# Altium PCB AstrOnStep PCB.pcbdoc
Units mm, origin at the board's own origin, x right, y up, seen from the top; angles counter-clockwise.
Board outline 107.04 x 79.7 mm, 4 copper layers (Top Layer, Inner1, Inner2, Bottom Layer); 79 components, 101 nets, 389 pads, 59 vias.
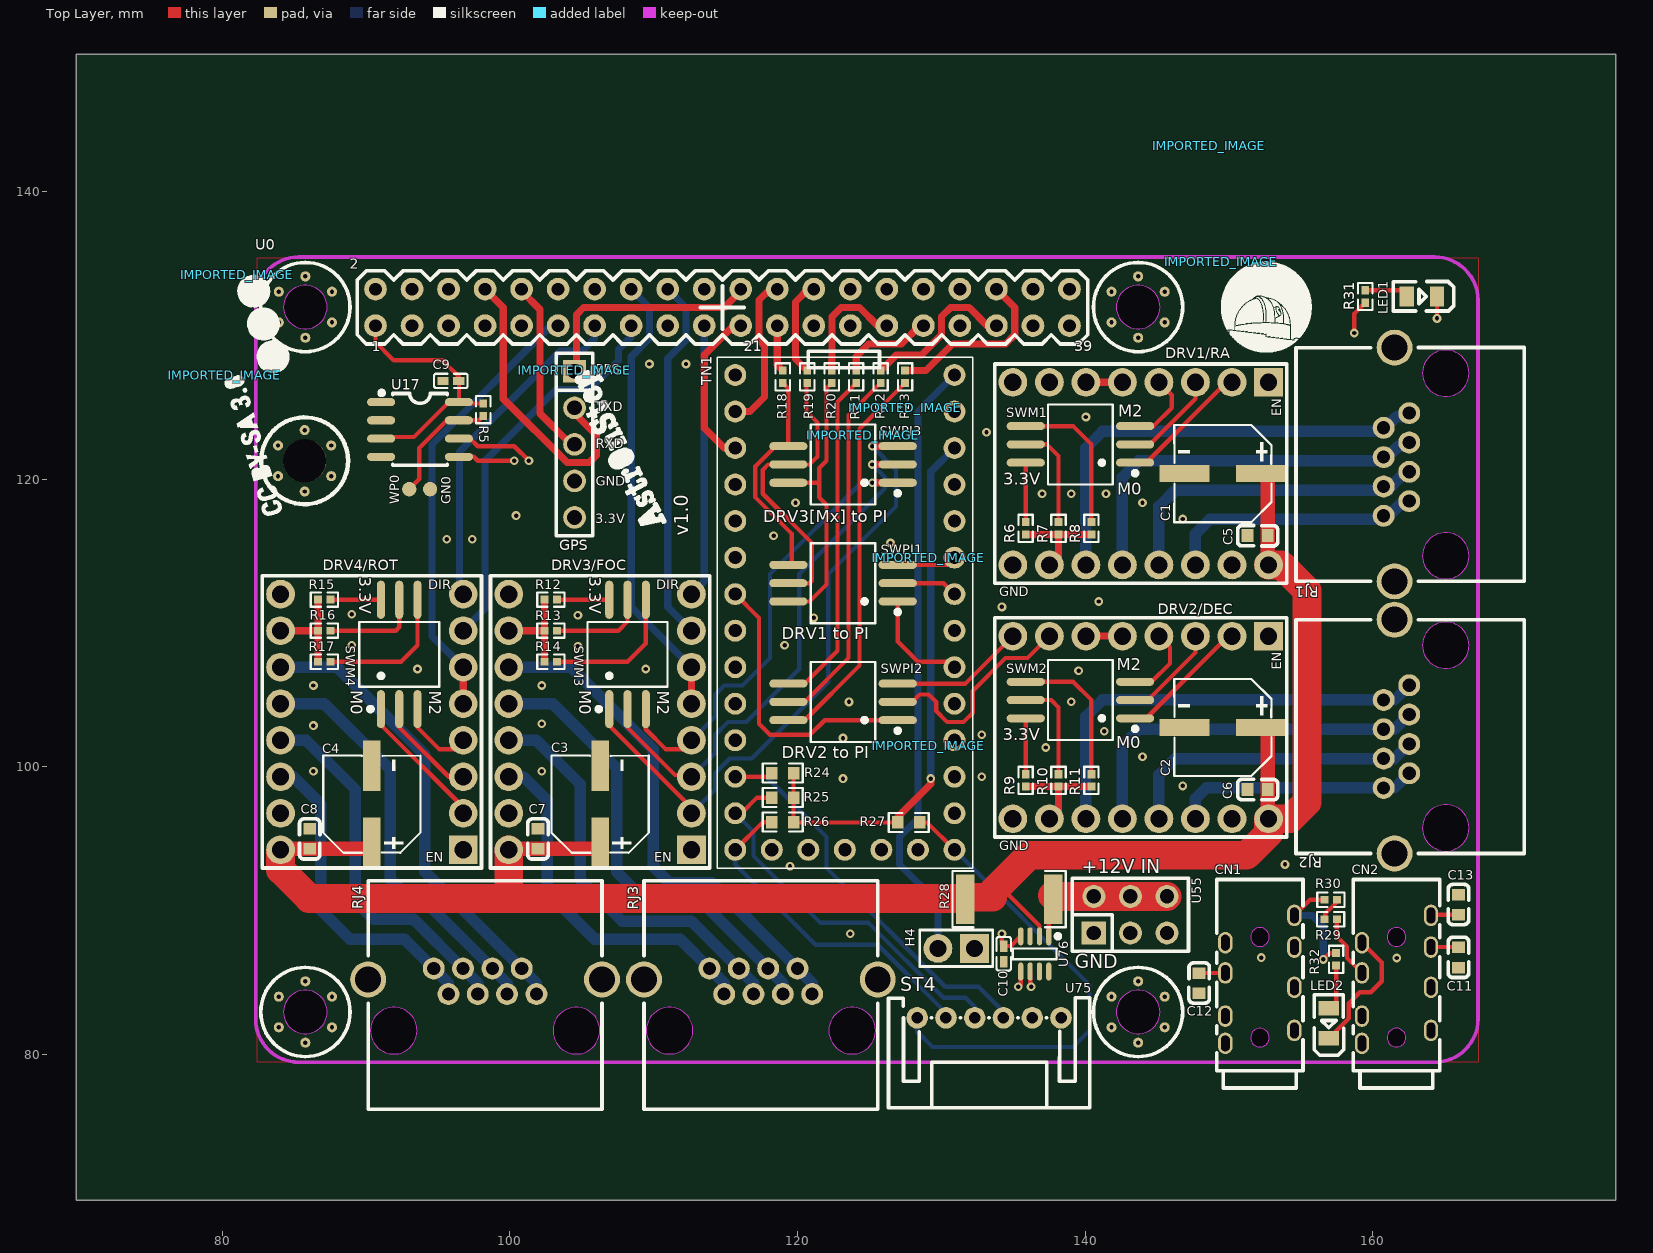
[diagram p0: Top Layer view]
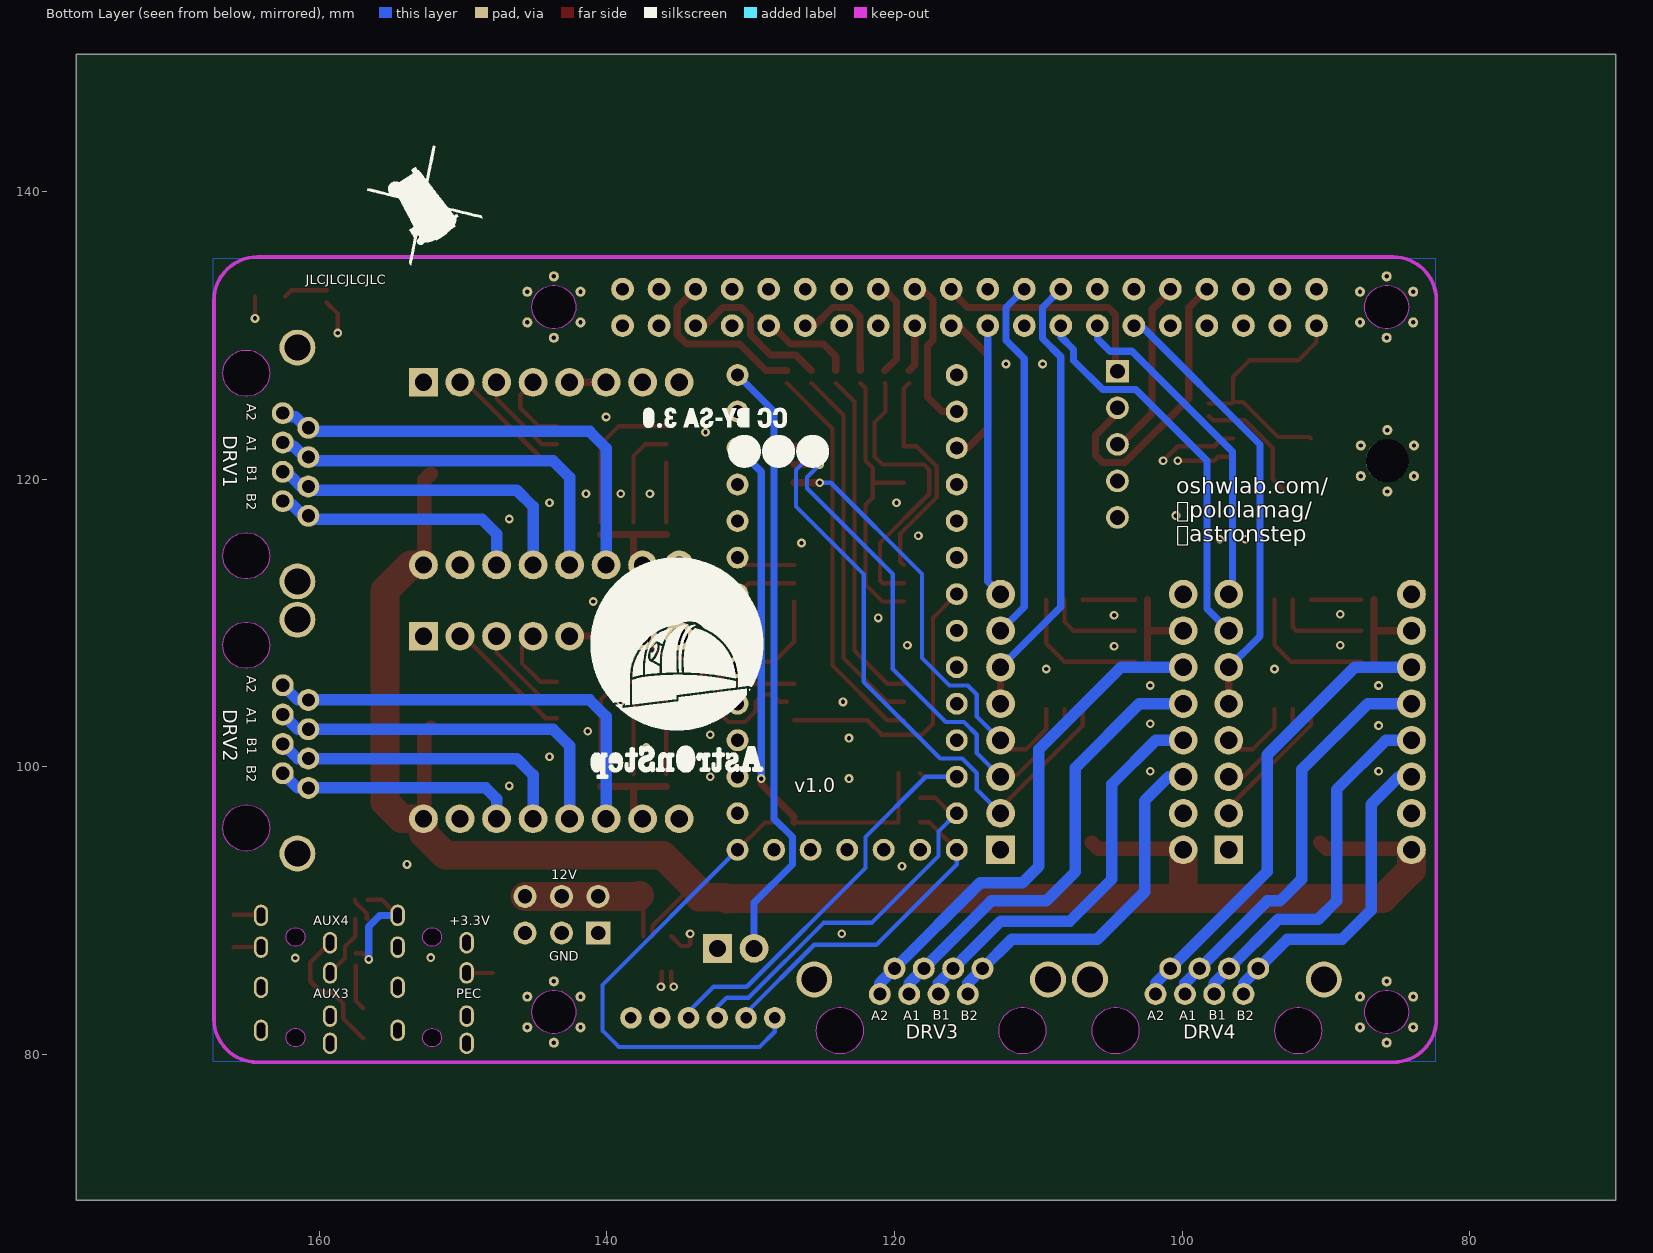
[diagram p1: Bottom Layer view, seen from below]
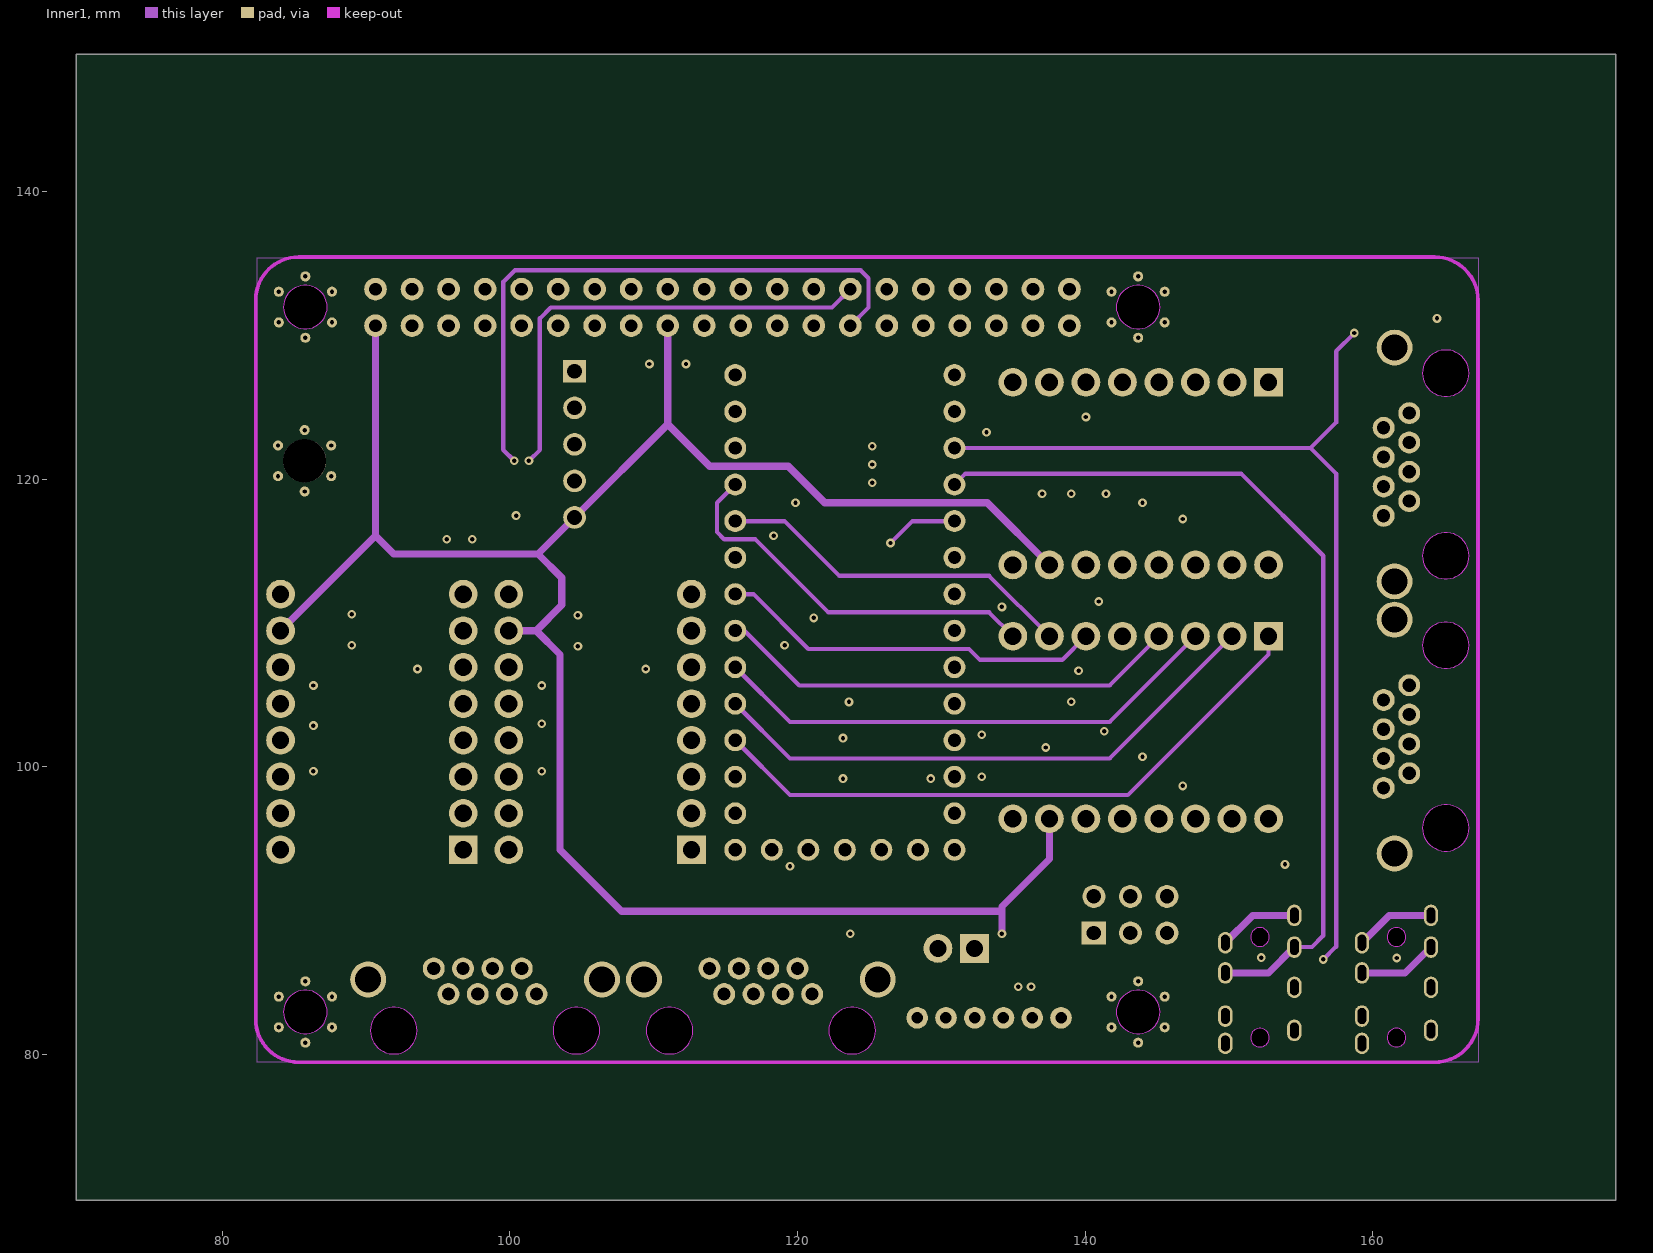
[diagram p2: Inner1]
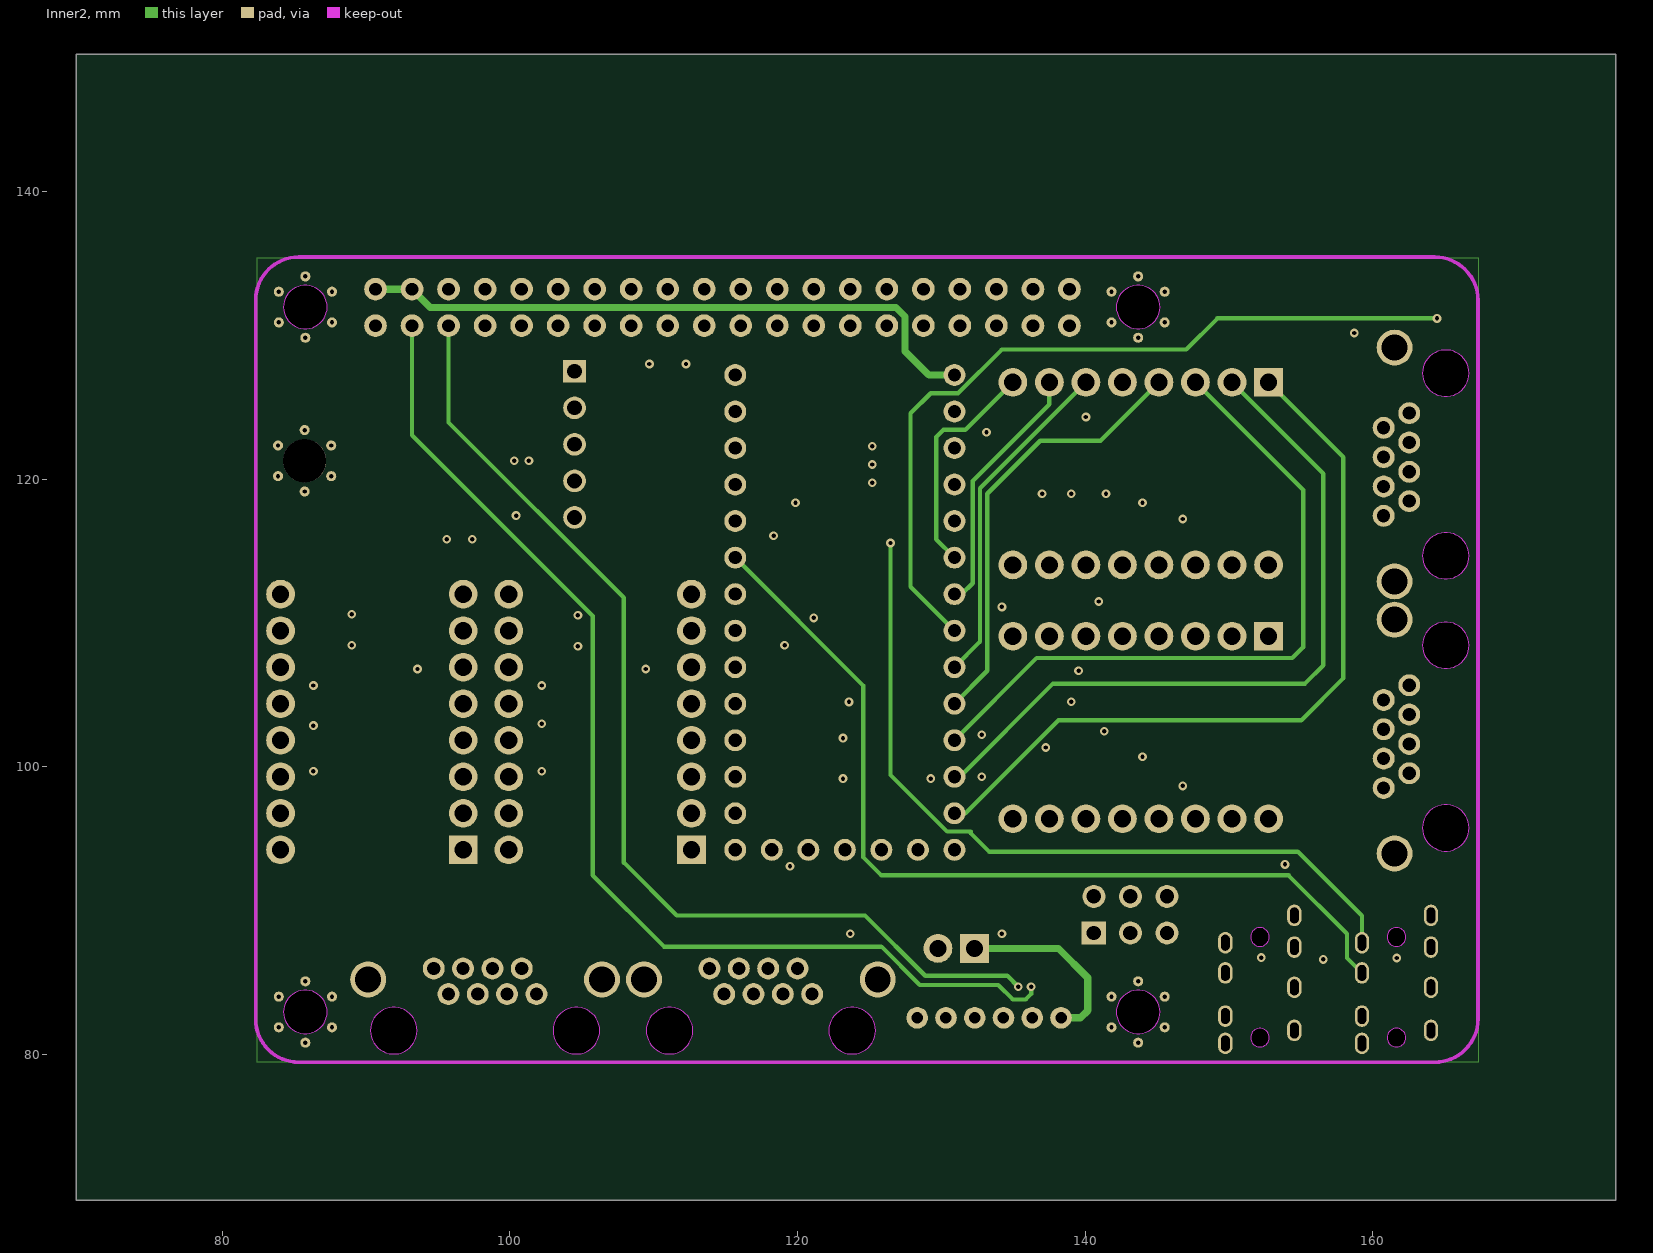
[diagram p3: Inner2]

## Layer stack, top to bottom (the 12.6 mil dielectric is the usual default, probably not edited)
Top Layer: signal copper (thickness not stored)
Dielectric: dielectric 0.32, FR-4, Dk 4.8
Inner1: signal copper (thickness not stored)
Dielectric: dielectric 0.32, FR-4, Dk 4.8
Inner2: signal copper (thickness not stored)
Dielectric: dielectric 0.32, FR-4, Dk 4.8
Bottom Layer: signal copper (thickness not stored)

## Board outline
176.891,69.85 69.85,69.85 69.85,149.55 176.891,149.55

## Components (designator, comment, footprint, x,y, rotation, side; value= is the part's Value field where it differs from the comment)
C1 "RST100UF25V004" CAP-SMD_BD6.3-L6.6-W6.6-LS7.3-FD 149.579,120.396 r180 top
C2 "RST100UF25V004" CAP-SMD_BD6.3-L6.6-W6.6-LS7.3-FD 149.579,102.743 r180 top
C3 "RST100UF25V004" CAP-SMD_BD6.3-L6.6-W6.6-LS7.3-FD 106.272,97.409 r90 top
C4 "RST100UF25V004" CAP-SMD_BD6.3-L6.6-W6.6-LS7.3-FD 90.397,97.409 r90 top
C5 "CC0603KRX7R9BB104" C0603 151.992,116.078 r180 top
C6 "CC0603KRX7R9BB104" C0603 151.992,98.425 r180 top
C7 "CC0603KRX7R9BB104" C0603 101.954,94.996 r90 top
C8 "CC0603KRX7R9BB104" C0603 86.079,94.996 r90 top
C9 "CL05B104KO5NNNC" C0402 95.891,126.845 r0 top
C10 "CL05B104KO5NNNC" C0402 134.339,86.995 r270 top
C11 "CC0603KRX7R9BB104" C0603 165.962,86.741 r270 top
C12 "CC0603KRX7R9BB104" C0603 147.928,84.963 r270 top
C13 "CC0603KRX7R9BB104" C0603 165.962,90.424 r270 top
CN1 "PJ-35372" audio-th_pj-35372 152.151,85.223 r180 top
CN2 "PJ-35372" audio-th_pj-35372 161.651,85.223 r180 top
DRV1/RA "TMC5160 v1.3" tmc5160 152.754,126.746 r270 top
DRV2/DEC "TMC5160 v1.3" tmc5160 152.754,109.093 r270 top
DRV3/FOC "TMC5160 v1.3" tmc5160 112.622,94.234 r180 top
DRV4/ROT "TMC5160 v1.3" tmc5160 96.747,94.234 r180 top
GN0 "Test-Point" test-point-0.5mm 94.444,119.315 r90 top
GPS "2.54-1*5P母" hdr-th_5p-p2.54-v-f 104.494,122.428 r270 top
H4 "PZ254V-11-02P" HDR-TH_2P-P2.54-V-M 131.037,87.376 r180 top
IMPORTED_IMAGE "IMPORTED_IMAGE" IMPORTED_IMAGE 127.481,124.968 r0 top
IMPORTED_IMAGE "IMPORTED_IMAGE" IMPORTED_IMAGE 124.56,123.063 r0 top
IMPORTED_IMAGE "IMPORTED_IMAGE" IMPORTED_IMAGE 148.624,143.2 r0 top
IMPORTED_IMAGE "IMPORTED_IMAGE" IMPORTED_IMAGE 129.132,114.554 r0 top
IMPORTED_IMAGE "IMPORTED_IMAGE" IMPORTED_IMAGE 129.132,101.473 r0 top
IMPORTED_IMAGE "IMPORTED_IMAGE" IMPORTED_IMAGE 80.159,127.226 r0 top
IMPORTED_IMAGE "IMPORTED_IMAGE" IMPORTED_IMAGE 81.05,134.213 r0 top
IMPORTED_IMAGE "IMPORTED_IMAGE" IMPORTED_IMAGE 104.509,127.575 r0 top
IMPORTED_IMAGE "IMPORTED_IMAGE" IMPORTED_IMAGE 149.452,135.128 r0 top
LED1 "NCD0805R1_C84256" LED0805-R-RD 163.422,132.715 r180 top
LED2 "NCD0805R1_C84256" LED0805-R-RD 156.945,82.169 r90 top
R5 "0402WGF1001TCE" R0402 98.144,124.841 r90 top
R6 "0402WGF3300TCE" R0402 135.863,116.586 r270 top
R7 "0402WGF3300TCE" R0402 138.149,116.586 r270 top
R8 "0402WGF3300TCE" R0402 140.435,116.586 r270 top
R9 "0402WGF3300TCE" R0402 135.863,99.06 r270 top
R10 "0402WGF3300TCE" R0402 138.149,99.06 r270 top
R11 "0402WGF3300TCE" R0402 140.435,99.06 r270 top
R12 "0402WGF3300TCE" R0402 102.843,111.633 r180 top
R13 "0402WGF3300TCE" R0402 102.843,109.474 r180 top
R14 "0402WGF3300TCE" R0402 102.843,107.315 r180 top
R15 "0402WGF3300TCE" R0402 87.095,111.633 r180 top
R16 "0402WGF3300TCE" R0402 87.095,109.474 r180 top
R17 "0402WGF3300TCE" R0402 87.095,107.315 r180 top
R18 "0402WGF3300TCE" R0402 118.972,127.127 r270 top
R19 "0402WGF3300TCE" R0402 120.674,127.127 r270 top
R20 "0402WGF3300TCE" R0402 122.376,127.127 r270 top
R21 "0402WGF3300TCE" R0402 124.077,127.127 r270 top
R22 "0402WGF3300TCE" R0402 125.779,127.127 r270 top
R23 "0402WGF3300TCE" R0402 127.481,127.127 r270 top
R24 "0603WAF2401T5E" R0603 118.972,99.568 r180 top
R25 "0603WAF2401T5E" R0603 118.972,97.864 r180 top
R26 "0603WAF2401T5E" R0603 118.972,96.16 r180 top
R27 "0603WAF2401T5E" R0603 127.735,96.139 r0 top
R28 "PA2512FKF7T0R005E" R2512 134.72,90.805 r0 top
R29 "0402WGF1001TCE" R0402 157.072,89.408 r180 top
R30 "0402WGF1001TCE" R0402 157.083,90.766 r0 top
R31 "0402WGF3301TCE" R0402 159.485,132.715 r270 top
R32 "0402WGF3301TCE" R0402 157.453,86.614 r90 top
RJ1 "R-RJ45R08P-B000" rj45-th_r-rj45r08p-b000#1 161.651,121.031 r90 top
RJ2 "R-RJ45R08P-B000" rj45-th_r-rj45r08p-b000#1 161.651,102.108 r90 top
RJ3 "R-RJ45R08P-B000" rj45-th_r-rj45r08p-b000#2 117.448,85.09 r0 top
RJ4 "R-RJ45R08P-B000" rj45-th_r-rj45r08p-b000#2 98.271,85.09 r0 top
SWM1 "DSHP03TS-S" SW-SMD_DSHP03TS-S 139.673,122.428 r90 top
SWM2 "DSHP03TS-S" SW-SMD_DSHP03TS-S 139.673,104.648 r90 top
SWM3 "DSHP03TS-S" SW-SMD_DSHP03TS-S 108.177,107.823 r0 top
SWM4 "DSHP03TS-S" SW-SMD_DSHP03TS-S 92.302,107.823 r0 top
SWPI1 "DSHP03TS-S" SW-SMD_DSHP03TS-S 123.163,112.776 r90 top
SWPI2 "DSHP03TS-S" SW-SMD_DSHP03TS-S 123.163,104.521 r90 top
SWPI3 "DSHP03TS-S" SW-SMD_DSHP03TS-S 123.163,121.031 r90 top
TN1 "Teensy4.0" teensy4.0 115.67,127.254 r0 top
U0 "RASPI HAT FULL" RASBERRYPI-3-HAT-EXT 90.651,133.223 r0 top
U17 "AT24C32D-SSHM-T" SOIC-8_L5.0-W4.0-P1.27-LS6.0-BL 93.747,123.467 r270 top
U55 "PM254-2-03-Z-8.5" hdr-th_6p-p2.54-v-f-r2-c3-s2.54 143.151,89.723 r0 top
U75 "S6B-PH-K-S(LF)(SN)" conn-th_6p-p2.00_s6b-ph-k-s-lf-sn 133.323,82.55 r0 top
U76 "INA219AIDCNR" SOT-23-8_L3.0-W1.7-P0.65-LS2.8-BR 136.498,86.995 r90 top
WP0 "Test-Point" test-point-0.5mm 92.998,119.315 r90 top

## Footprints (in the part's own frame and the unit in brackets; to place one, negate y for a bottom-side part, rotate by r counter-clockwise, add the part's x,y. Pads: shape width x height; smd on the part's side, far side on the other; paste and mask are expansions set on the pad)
audio-th_pj-35372 [mm]
  oval 1x1.5 hole 0.6 slot 1.1 at 90 deg: 1(-2.4,3.55) 2(-2.4,0.55) 3(-2.4,-2.25) 4(-2.4,-4.45) 5(2.4,4.45) 6(2.4,2.55) 7(2.4,-0.45) 8(2.4,-2.55)
  Multi-Layer board cut-out: -0.65,4.05 -0.586,3.768 -0.405,3.542 -0.145,3.416 0.145,3.416 0.405,3.542 0.586,3.768 0.65,4.05 0.65,4.05 0.586,4.332 0.405,4.558 0.145,4.684 -0.145,4.684 -0.405,4.558 -0.586,4.332 -0.65,4.05
  Multi-Layer board cut-out: -0.65,-2.95 -0.586,-3.232 -0.405,-3.458 -0.145,-3.584 0.145,-3.584 0.405,-3.458 0.586,-3.232 0.65,-2.95 0.65,-2.95 0.586,-2.668 0.405,-2.442 0.145,-2.316 -0.145,-2.316 -0.405,-2.442 -0.586,-2.668 -0.65,-2.95
  Multi-Layer keep-out region: -0.65,4.05 -0.586,3.768 -0.405,3.542 -0.145,3.416 0.145,3.416 0.405,3.542 0.586,3.768 0.65,4.05 0.65,4.05 0.586,4.332 0.405,4.558 0.145,4.684 -0.145,4.684 -0.405,4.558 -0.586,4.332 -0.65,4.05
  Multi-Layer keep-out region: -0.65,-2.95 -0.586,-3.232 -0.405,-3.458 -0.145,-3.584 0.145,-3.584 0.405,-3.458 0.586,-3.232 0.65,-2.95 0.65,-2.95 0.586,-2.668 0.405,-2.442 0.145,-2.316 -0.145,-2.316 -0.405,-2.442 -0.586,-2.668 -0.65,-2.95
  silkscreen extent -3,-6.95 3,7.55
C0402 [mm]
  rect 0.79x0.54 smd: 1(-0.545,0) 2(0.545,0)
  silkscreen extent -1.17,-0.5 1.17,0.5
C0603 [mm]
  rect 0.8x0.9 smd: 1(-0.7,0) 2(0.7,0)
  silkscreen extent -1.41,-0.71 1.39,0.72
CAP-SMD_BD6.3-L6.6-W6.6-LS7.3-FD [mm]
  rect 3.5x1.2 smd: 1(-2.67,0) 2(2.67,0)
  silkscreen extent -3.38,-3.38 3.38,3.38
conn-th_6p-p2.00_s6b-ph-k-s-lf-sn [mm]
  round 1.5 hole 0.8: 1(-5,0) 2(-3,0) 3(-1,0) 4(1,0) 5(3,0) 6(5,0)
  silkscreen extent -7,-6.25 7,1.4
HDR-TH_2P-P2.54-V-M [mm]
  rect 2x2 hole 1.2: 1(-1.27,0)
  round 2 hole 1.2: 2(1.27,0)
  silkscreen extent -2.54,-1.27 2.54,1.27
hdr-th_5p-p2.54-v-f [mil]
  rect 62x62 hole 40.16: 1(-200,0)
  round 62 hole 40.16: 2(-100,0) 3(0,0) 4(100,0) 5(200,0)
  silkscreen extent -250,-50 250,50
hdr-th_6p-p2.54-v-f-r2-c3-s2.54 [mm]
  rect 1.7x1.6 hole 1: 1(-2.54,-1.27)
  round 1.6 hole 1: 2(-2.54,1.27) 3(0,-1.27) 4(0,1.27) 5(2.54,-1.27) 6(2.54,1.27)
  silkscreen extent -4.04,-2.54 4.04,2.54
IMPORTED_IMAGE [mm]
LED0805-R-RD [mm]
  rect 1x1.4 smd: 1(1.05,0) 2(-1.05,0)
  silkscreen extent -2.22,-1.04 1.99,1.01
R0402 [mm]
  rect 0.566x0.54 smd: 1(-0.433,0) 2(0.433,0)
  silkscreen extent -0.94,-0.5 0.94,0.5
R0603 [mm]
  rect 0.806x0.864 smd: 1(-0.753,0) 2(0.753,0)
  silkscreen extent -1.39,-0.66 1.39,0.66
R2512 [mm]
  rect 1.283x3.456 smd: 1(-3.066,0) 2(3.066,0)
  silkscreen extent -3.94,-1.96 3.94,1.96
RASBERRYPI-3-HAT-EXT [mil]
  round 62 hole 35: 1(0,-100) 2(0,0) 3(100,-100) 4(100,0) 5(200,-100) 6(200,0) 7(300,-100) 8(300,0) 9(400,-100) 10(400,0) 11(500,-100) 12(500,0) 13(600,-100) 14(600,0) 15(700,-100) 16(700,0) 17(800,-100) 18(800,0) 19(900,-100) 20(900,0) 21(1000,-100) 22(1000,0) 23(1100,-100) 24(1100,0) 25(1200,-100) 26(1200,0) 27(1300,-100) 28(1300,0) 29(1400,-100) 30(1400,0) 31(1500,-100) 32(1500,0) 33(1600,-100) 34(1600,0) 35(1700,-100) 36(1700,0) 37(1800,-100) 38(1800,0) 39(1900,-100) 40(1900,0)
  round 27.56 hole 11.81: 41(-192,-1895) 41(-192,35) 41(2088,-1895) 41(2088,35) 42(-264.75,-1937) 42(-264.75,-7) 42(2015.25,-1937) 42(2015.25,-7) 43(-264.75,-2021) 43(-264.75,-91) 43(2015.25,-2021) 43(2015.25,-91) 44(-192,-2063) 44(-192,-133) 44(2088,-2063) 44(2088,-133) 45(-119.25,-2021) 45(-119.25,-91) 45(2160.75,-2021) 45(2160.75,-91) 46(-119.25,-1937) 46(-119.25,-7) 46(2160.75,-1937) 46(2160.75,-7)
  Board Outline Layer lines w10: -210,-2116.62 2900.23,-2116.62 ; -210,-2116.62 2900.23,-2116.62 ; -210,-2116.61 cw(c-210,-1998.5) -328.11,-1998.5 ccw(c-210,-1998.5) -210,-2116.61 ; -210,88.11 2900.23,88.11 ; -210,88.11 2900.23,88.11 ; -210,88.11 ccw(c-210,-30) -328.11,-30 cw(c-210,-30) -210,88.11 ; 2900.24,-2116.61 ccw(c2900.24,-1998.5) 3018.35,-1998.5 ; 2900.24,-2116.61 ccw(c2900.24,-1998.5) 3018.35,-1998.5 ; 2900.24,88.11 cw(c2900.24,-30) 3018.35,-30 ; 2900.24,88.11 cw(c2900.24,-30) 3018.35,-30 ; 3018.34,-1998.51 3018.34,-30 ; 3018.34,-1998.51 3018.34,-30 ; -328,-1998 -328,-29.5 -328,-1998
  Multi-Layer board cut-out: 2148,-49 2139.81,-19.19 2117.87,2.59 2088,10.55 2058.13,2.59 2036.19,-19.19 2028,-49 2028,-49 2036.19,-78.81 2058.13,-100.59 2088,-108.56 2117.87,-100.59 2139.81,-78.81 2148,-49
  Multi-Layer board cut-out: -132,-49 -140.19,-19.19 -162.13,2.59 -192,10.55 -221.87,2.59 -243.81,-19.19 -252,-49 -252,-49 -243.81,-78.81 -221.87,-100.59 -192,-108.56 -162.13,-100.59 -140.19,-78.81 -132,-49
  Multi-Layer board cut-out: -132,-1979 -140.19,-1949.19 -162.13,-1927.41 -192,-1919.45 -221.87,-1927.41 -243.81,-1949.19 -252,-1979 -252,-1979 -243.81,-2008.81 -221.87,-2030.59 -192,-2038.56 -162.13,-2030.59 -140.19,-2008.81 -132,-1979
  Multi-Layer board cut-out: 2148,-1979 2139.81,-1949.19 2117.87,-1927.41 2088,-1919.45 2058.13,-1927.41 2036.19,-1949.19 2028,-1979 2028,-1979 2036.19,-2008.81 2058.13,-2030.59 2088,-2038.56 2117.87,-2030.59 2139.81,-2008.81 2148,-1979
  Multi-Layer keep-out region: 2148,-49 2139.81,-19.19 2117.87,2.59 2088,10.55 2058.13,2.59 2036.19,-19.19 2028,-49 2028,-49 2036.19,-78.81 2058.13,-100.59 2088,-108.56 2117.87,-100.59 2139.81,-78.81 2148,-49
  Multi-Layer keep-out region: -132,-49 -140.19,-19.19 -162.13,2.59 -192,10.55 -221.87,2.59 -243.81,-19.19 -252,-49 -252,-49 -243.81,-78.81 -221.87,-100.59 -192,-108.56 -162.13,-100.59 -140.19,-78.81 -132,-49
  Multi-Layer keep-out region: -132,-1979 -140.19,-1949.19 -162.13,-1927.41 -192,-1919.45 -221.87,-1927.41 -243.81,-1949.19 -252,-1979 -252,-1979 -243.81,-2008.81 -221.87,-2030.59 -192,-2038.56 -162.13,-2030.59 -140.19,-2008.81 -132,-1979
  Multi-Layer keep-out region: 2148,-1979 2139.81,-1949.19 2117.87,-1927.41 2088,-1919.45 2058.13,-1927.41 2036.19,-1949.19 2028,-1979 2028,-1979 2036.19,-2008.81 2058.13,-2030.59 2088,-2038.56 2117.87,-2030.59 2139.81,-2008.81 2148,-1979
  silkscreen extent -314,-2101 2210,73
rj45-th_r-rj45r08p-b000#1 [mil]
  round 60 hole 36: 1(140.55,-35.04) 2(100.39,35.04) 3(60.24,-35.05) 4(20.08,35.04) 5(-20.08,-35.04) 6(-60.24,35.04) 7(-100.39,-35.05) 8(-140.55,35.04)
  round 98.42 hole 70.87: 9(-320.08,5.12) 10(320.08,5.12)
  Multi-Layer board cut-out: 250,-199.02 281.78,-190.28 305,-166.89 313.49,-135.04 305,-103.19 281.78,-79.8 250,-71.07 250,-71.07 218.22,-79.8 195,-103.19 186.51,-135.04 195,-166.89 218.22,-190.28 250,-199.02
  Multi-Layer board cut-out: -250,-199.02 -218.22,-190.28 -195,-166.89 -186.51,-135.04 -195,-103.19 -218.22,-79.8 -250,-71.07 -250,-71.07 -281.78,-79.8 -305,-103.19 -313.49,-135.04 -305,-166.89 -281.78,-190.28 -250,-199.02
  Multi-Layer keep-out region: 250,-199.02 281.78,-190.28 305,-166.89 313.49,-135.04 305,-103.19 281.78,-79.8 250,-71.07 250,-71.07 218.22,-79.8 195,-103.19 186.51,-135.04 195,-166.89 218.22,-190.28 250,-199.02
  Multi-Layer keep-out region: -250,-199.02 -218.22,-190.28 -195,-166.89 -186.51,-135.04 -195,-103.19 -218.22,-79.8 -250,-71.07 -250,-71.07 -281.78,-79.8 -305,-103.19 -313.49,-135.04 -305,-166.89 -281.78,-190.28 -250,-199.02
  silkscreen extent -320,-350 320,275
rj45-th_r-rj45r08p-b000#2 [mil]
  round 60 hole 36: 1(140.55,-35.04) 2(100.39,35.04) 3(60.24,-35.04) 4(20.08,35.04) 5(-20.08,-35.04) 6(-60.24,35.04) 7(-100.39,-35.04) 8(-140.55,35.04)
  round 98.42 hole 70.87: 9(-320.08,5.12) 10(320.08,5.12)
  Multi-Layer board cut-out: 313.98,-135.04 307.64,-107.28 289.89,-85.02 264.24,-72.67 235.76,-72.67 210.11,-85.02 192.36,-107.28 186.02,-135.04 186.02,-135.04 192.36,-162.8 210.11,-185.06 235.76,-197.41 264.24,-197.41 289.89,-185.06 307.64,-162.8 313.98,-135.04
  Multi-Layer board cut-out: -186.02,-135.04 -192.36,-107.28 -210.11,-85.02 -235.76,-72.67 -264.24,-72.67 -289.89,-85.02 -307.64,-107.28 -313.98,-135.04 -313.98,-135.04 -307.64,-162.8 -289.89,-185.06 -264.24,-197.41 -235.76,-197.41 -210.11,-185.06 -192.36,-162.8 -186.02,-135.04
  Multi-Layer keep-out region: 313.98,-135.04 307.64,-107.28 289.89,-85.02 264.24,-72.67 235.76,-72.67 210.11,-85.02 192.36,-107.28 186.02,-135.04 186.02,-135.04 192.36,-162.8 210.11,-185.06 235.76,-197.41 264.24,-197.41 289.89,-185.06 307.64,-162.8 313.98,-135.04
  Multi-Layer keep-out region: -186.02,-135.04 -192.36,-107.28 -210.11,-85.02 -235.76,-72.67 -264.24,-72.67 -289.89,-85.02 -307.64,-107.28 -313.98,-135.04 -313.98,-135.04 -307.64,-162.8 -289.89,-185.06 -264.24,-197.41 -235.76,-197.41 -210.11,-185.06 -192.36,-162.8 -186.02,-135.04
  silkscreen extent -320,-350 320,275
SOIC-8_L5.0-W4.0-P1.27-LS6.0-BL [mil]
  oval 22.38x76.78 smd: 1(-75,-106.5) 2(-25,-106.5) 3(25,-106.5) 4(75,-106.5) 5(75,106.5) 6(25,106.5) 7(-25,106.5) 8(-75,106.5)
  silkscreen extent -106,-111 98,75
SOT-23-8_L3.0-W1.7-P0.65-LS2.8-BR [mm]
  oval 1.252x0.364 smd: 1(1.226,-0.975) 2(1.226,-0.325) 3(1.226,0.325) 4(1.226,0.975) 5(-1.226,0.975) 6(-1.226,0.325) 7(-1.226,-0.325) 8(-1.226,-0.975)
  silkscreen extent -0.37,-1.76 1.38,1.53
SW-SMD_DSHP03TS-S [mm]
  oval 0.56x2.655 smd: 1(-1.27,-3.803) 2(0,-3.803) 3(1.27,-3.803) 4(1.27,3.803) 5(0,3.803) 6(-1.27,3.803)
  silkscreen extent -2.78,-3.95 2.78,2.25
teensy4.0 [mil]
  round 60 hole 36: 0(0,-100) 1(0,-200) 2(0,-300) 3(0,-400) 4(0,-500) 5(0,-600) 6(0,-700) 7(0,-800) 8(0,-900) 9(0,-1000) 10(0,-1100) 11(0,-1200) 12(0,-1300) 13(600,-1300) 14(600,-1200) 15(600,-1100) 16(600,-1000) 17(600,-900) 18(600,-800) 19(600,-700) 20(600,-600) 21(600,-500) 22(600,-400) 23(600,-300) 24(600,-200) 25(100,-1300) 26(200,-1300) 27(300,-1300) 28(400,-1300) 29(500,-1300) G1(0,0) G2(600,-100) Vin(600,0)
  silkscreen extent -50,-1351 650,65
test-point-0.5mm [mm]
  round 1 smd: 1(0,0)
tmc5160 [mm]
  rect 2x2 hole 1.2: 1(0,0)
  round 2 hole 1.2: 2(0,-2.54) 3(0,-5.08) 4(0,-7.62) 5(0,-10.16) 6(0,-12.7) 7(0,-15.24) 8(0,-17.78) 9(12.7,-17.78) 10(12.7,-15.24) 11(12.7,-12.7) 12(12.7,-10.16) 13(12.7,-7.62) 14(12.7,-5.08) 15(12.7,-2.54) 16(12.7,0)
  silkscreen extent -1.27,-19.05 13.97,1.27

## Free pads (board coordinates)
  round 3 hole 3 unplated: 15(85.724,121.288)
  round 0.7 hole 0.3: 41(85.724,123.422) 42(83.876,122.355) 43(83.876,120.221) 44(85.724,119.154) 45(87.572,120.221) 46(87.572,122.355)

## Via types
v1: diameter 0.61, hole 0.305, Top Layer to Bottom Layer, 59 vias

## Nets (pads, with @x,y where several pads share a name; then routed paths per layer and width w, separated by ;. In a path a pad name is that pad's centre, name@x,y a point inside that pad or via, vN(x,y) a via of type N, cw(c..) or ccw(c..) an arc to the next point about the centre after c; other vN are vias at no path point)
1-WIRE: U0.7
$2N62787: R5.1 U17.7 WP0.1 | length 8.5
  Top Layer w0.3: WP0.1 93.699,120.016 93.699,122.174 95.627,124.102 U17.7 97.838,124.102 R5.1
$2N104513: H4.1 U75.6 | length 13.1
  Inner2 w0.5: H4.1 138.149,87.376 140.181,85.344 140.181,83.05 139.681,82.55 U75.6
$2N105510: R18.1 U0.23 | length 3.3
  Top Layer w0.5: U0.23 118.591,127.941 R18.1
$2N105512: R19.1 U0.26 | length 6.7
  Top Layer w0.5: R19.1 119.861,128.373 119.861,132.334 120.75,133.223 U0.26
$2N105514: R20.1 U0.29 | length 8.4
  Top Layer w0.5: R20.1 122.376,128.335 122.388,128.347 122.388,131.305 123.036,131.953 124.306,131.953 125.576,130.683 U0.29
$2N105697: R21.1 U0.31 | length 6.5
  Top Layer w0.5: R21.1 124.077,128.549 124.941,129.413 127.227,129.413 128.497,130.683 U0.31
$2N105699: R22.1 U0.35 | length 11.1
  Top Layer w0.5: R22.1 126.87,128.651 128.624,128.651 130.021,130.048 130.021,131.318 130.648,131.945 131.934,131.945 133.196,130.683 U0.35
$2N105701: R23.1 U0.36 | length 12.4
  Top Layer w0.5: R23.1 128.93,127.56 130.783,129.413 134.466,129.413 135.101,130.048 135.101,131.953 U0.36
$2N106392: LED1.1 R31.1 | length 3.1
  Top Layer w0.3: R31.1 161.939,133.148 LED1.1
$2N106431: LED2.1 R32.1 | length 3.2
  Top Layer w0.3: LED2.1 157.453,83.727 R32.1
$2N106601: R29.2 R30.2 | length 1.7
  Top Layer w0.3: R29.2 156.691,89.46 156.691,89.789 157.516,90.614 R30.2
$9N9567: R15.1 SWM4.6 | length 3.5
  Top Layer w0.3: R15.1 88.88,111.633 88.888,111.626 SWM4.6
$9N9568: R17.1 SWM4.4 | length 9.7
  Top Layer w0.3: R17.1 92.429,107.315 93.572,108.458 SWM4.4
$9N9569: R16.1 SWM4.5 | length 6.8
  Top Layer w0.3: R16.1 92.056,109.474 92.302,109.72 SWM4.5
$9N9693: R14.1 SWM3.4 | length 9.7
  Top Layer w0.3: R14.1 108.177,107.315 109.447,108.585 SWM3.4
$9N9694: R12.1 SWM3.6 | length 3.6
  Top Layer w0.3: R12.1 106.907,111.633 SWM3.6
$9N9695: R13.1 SWM3.5 | length 6.7
  Top Layer w0.3: R13.1 107.542,109.474 108.177,110.109 SWM3.5
$9N9819: R11.1 SWM2.4 | length 10.2
  Top Layer w0.3: SWM2.4 139.165,105.918 140.435,104.648 R11.1
$9N9820: R9.1 SWM2.6 | length 3.9
  Top Layer w0.3: R9.1 135.863,103.371 SWM2.6
$9N9821: R10.1 SWM2.5 | length 7.1
  Top Layer w0.3: SWM2.5 137.641,104.648 138.149,104.14 R10.1
$9N9945: R6.1 SWM1.6 | length 4.1
  Top Layer w0.3: R6.1 135.87,117.026 SWM1.6
$9N9946: R8.1 SWM1.4 | length 10.5
  Top Layer w0.3: SWM1.4 139.165,123.698 140.435,122.428 R8.1
$9N9947: R7.1 SWM1.5 | length 7.2
  Top Layer w0.3: SWM1.5 137.348,122.428 138.149,121.627 R7.1
+3.3T: CN1.4 CN1.8 R24.1 R25.1 R26.1 R27.1 R30.1 R31.2 R32.2 TN1.24 | length 125.3
  Top Layer w0.3: R24.1 R25.1 R26.1 119.747,96.139 R27.1 ; CN1.4 155.644,90.766 R30.1 ; v1(156.564,86.614) 156.997,87.047 R32.2 ; v1(158.723,130.175) 158.723,131.52 R31.2
  Top Layer w0.5: R27.1 126.982,96.529 129.259,98.806 v1(129.259,99.187)
  Inner1 w0.3: TN1.24 155.675,122.174 ; v1(156.564,86.614) 157.453,87.503 157.453,120.396 155.675,122.174 ; v1(158.723,130.175) 157.453,128.905 157.453,123.952 155.675,122.174
  Inner1 w0.5: CN1.8 151.651,89.673 CN1.4
  Bottom Layer w0.5: v1(129.259,99.187) 129.259,120.523 TN1.24 ; CN1.4 155.791,89.673 156.564,88.9 v1(156.564,86.614)
+3.3V: C9.2 C10.1 DRV1/RA.10 DRV2/DEC.10 DRV3/FOC.10 DRV4/ROT.10 GPS.5 R5.2 R6.2 R7.2 R8.2 R9.2 R10.2 R11.2 R12.2 R13.2 R14.2 R15.2 R16.2 R17.2 U0.1 U0.17 U17.3 U17.8 U76.4 | length 200.5
  Top Layer w0.3: U0.1 90.651,129.54 91.921,128.27 95.319,128.27 96.436,127.153 C9.2 96.452,126.829 U17.8 ; U17.3 91.146,122.936 93.318,122.936 95.754,125.372 U17.8 ; R5.2 96.55,125.274 U17.8 ; v1(134.212,88.392) 134.212,87.667 C10.1 134.842,87.54 U76.4
  Top Layer w0.5: DRV4/ROT.10 R16.2 ; R17.2 R16.2 ; R15.2 R16.2 ; DRV3/FOC.10 R13.2 ; R14.2 R13.2 ; R12.2 R13.2 ; R9.2 R10.2 ; R6.2 R7.2 ; DRV2/DEC.10 138.149,97.028 R10.2 ; DRV1/RA.10 138.149,114.681 R7.2 ; R11.2 R10.2 ; R8.2 R7.2
  Inner1 w0.5: DRV4/ROT.10 90.651,116.078 ; U0.1 90.651,116.078 ; DRV3/FOC.10 101.827,109.474 ; U0.17 110.971,123.825 ; v1(134.212,88.392) 134.212,89.963 ; DRV2/DEC.10 137.514,93.599 134.212,90.297 134.212,89.963 ; DRV1/RA.10 133.196,118.364 121.893,118.364 119.353,120.904 113.892,120.904 110.971,123.825 ; 90.651,116.078 91.921,114.808 101.954,114.808 ; 101.827,109.474 103.605,111.252 103.605,113.157 101.954,114.808 ; 101.827,109.474 103.478,107.823 103.478,94.234 107.749,89.963 134.212,89.963 ; 101.954,114.808 GPS.5 110.971,123.825
+5V_PI: H4.2 TN1.Vin U0.2 U0.4 | length 86.7
  Inner2 w0.5: U0.2 U0.4 94.461,131.953 126.846,131.953 127.481,131.318 127.481,128.905 129.132,127.254 TN1.Vin
  Bottom Layer w0.5: H4.2 129.767,90.551 127.1,93.218 127.1,95.123 128.37,96.393 128.37,124.714 TN1.Vin
+12V: C1.1 C2.1 C3.1 C4.1 C5.1 C6.1 C7.1 C8.1 DRV1/RA.16 DRV2/DEC.16 DRV3/FOC.16 DRV4/ROT.16 R28.1 U76.2 | length 130.1
  Top Layer w0.3: 133.577,90.932 133.958,91.313 134.466,91.313 136.823,88.956 U76.2
  Top Layer w1: DRV4/ROT.16 84.109,94.296 C8.1 89.954,94.296 C4.1 ; DRV3/FOC.16 99.984,94.296 C7.1 105.829,94.296 C3.1 ; C2.1 152.692,102.3 C6.1 152.692,96.455 DRV2/DEC.16 ; C1.1 152.692,119.953 C5.1 152.692,114.108 DRV1/RA.16
  Top Layer w2: DRV4/ROT.16@84.047,94.107 84.047,92.837 86.027,90.857 100.3,90.857 ; DRV3/FOC.16 99.922,91.235 100.3,90.857 ; DRV1/RA.16 153.643,114.046 155.421,112.268 155.421,97.536 154.278,96.393 DRV2/DEC.16 152.754,95.377 151.23,93.853 136.117,93.853 133.577,91.313 133.577,90.932 131.781,90.932 R28.1 131.602,90.857 100.3,90.857
+12V_DI: R28.2 U55.2 U55.4 U55.6 U76.1 | length 10.9
  Top Layer w0.3: U76.1 137.473,90.809 R28.2@137.723,91.059
  Top Layer w2: R28.2@137.723,91.059 137.789,90.993 U55.2 U55.4 U55.6
AUX0: LED1.2 TN1.19 | length 57.2
  Top Layer w0.3: v1(164.472,131.191) LED1.2
  Inner2 w0.3: TN1.19 127.862,112.522 127.862,124.587 129.259,125.984 131.164,125.984 134.212,129.032 147.039,129.032 149.198,131.191 v1(164.472,131.191)
AUX3: C11.1 CN2.3 CN2.7 R29.1 TN1.4 | length 75.5
  Top Layer w0.3: R29.1 157.505,88.213 158.215,87.503 158.215,86.709 CN2.7 ; CN2.3 165.93,87.473 C11.1
  Inner1 w0.5: CN2.7 162.251,85.673 CN2.3
  Inner2 w0.3: TN1.4 124.56,105.664 124.56,93.726 125.83,92.456 154.151,92.456 158.215,88.392 158.215,86.709 CN2.7
AUX4: C13.2 CN2.4 CN2.8 LED2.2 TN1.22 | length 76.7
  Top Layer w0.3: LED2.2 158.342,82.516 158.342,83.566 159.104,84.328 159.866,84.328 160.628,85.09 160.628,86.396 CN2.8 ; CN2.4 164.102,89.724 C13.2
  Inner1 w0.3: v1(126.465,115.57) 127.989,117.094 TN1.22
  Inner1 w0.5: CN2.8 161.151,89.673 CN2.4
  Inner2 w0.3: v1(126.465,115.57) 126.465,99.441 130.402,95.504 132.053,95.504 132.053,95.377 133.323,94.107 154.786,94.107 159.251,89.642 CN2.8
DE+: R26.2 TN1.12 U75.2 | length 23.6
  Top Layer w0.3: TN1.12 117.596,96.16 R26.2
  Bottom Layer w0.3: TN1.12 115.67,93.218 121.258,87.63 125.576,87.63 130.323,82.883 U75.2
DE-: R25.2 TN1.11 U75.3 | length 27
  Top Layer w0.3: TN1.11 116.094,96.774 117.184,97.864 R25.2
  Bottom Layer w0.3: TN1.11 116.94,95.504 116.94,93.807 121.593,89.154 124.941,89.154 130.148,83.947 131.672,83.947 132.323,83.296 U75.3
DRV1_1A: DRV1/RA.12 RJ1.3 RJ1.4 | length 26.9
  Bottom Layer w0.8: DRV1/RA.12 142.594,120.142 143.739,121.287 160.757,121.287 161.777,122.307 RJ1.3@162.534,122.307
DRV1_1B: DRV1/RA.11 RJ1.1 RJ1.2 | length 31.5
  Bottom Layer w0.8: DRV1/RA.11 140.054,122.174 141.207,123.327 160.638,123.327 161.658,124.347 RJ1.1@162.534,124.347
DRV1_2A: DRV1/RA.13 RJ1.5 RJ1.6 | length 22.4
  Bottom Layer w0.8: DRV1/RA.13 145.134,118.11 146.271,119.247 161.003,119.247 162.023,120.267 RJ1.5@162.534,120.267
DRV1_2B: DRV1/RA.14 RJ1.7 RJ1.8 | length 17.9
  Bottom Layer w0.8: DRV1/RA.14 147.674,116.205 148.676,117.207 160.868,117.207 161.888,118.227 RJ1.7@162.534,118.227
DRV1_DIR: DRV1/RA.8 SWPI1.3 TN1.21 | length 20
  Top Layer w0.3: SWPI1.3 130.402,114.046 TN1.21
  Inner2 w0.3: TN1.21 129.64,115.824 129.64,122.936 130.148,123.444 131.672,123.444 DRV1/RA.8
DRV1_EN: DRV1/RA.1 TN1.14 | length 53.7
  Inner2 w0.3: TN1.14 131.672,96.774 138.149,103.251 155.04,103.251 157.961,106.172 157.961,121.539 DRV1/RA.1
DRV1_M0: DRV1/RA.2 SWM1.1 TN1.15 | length 60.2
  Top Layer w0.3: SWM1.1 144.245,121.158 149.833,126.746 DRV1/RA.2
  Inner2 w0.3: TN1.15 131.291,99.314 137.768,105.791 155.294,105.791 156.564,107.061 156.564,120.396 DRV1/RA.2
DRV1_M1: DRV1/RA.3 SWM1.2 TN1.16 | length 55.1
  Top Layer w0.3: SWM1.2 144.499,122.428 147.674,125.603 DRV1/RA.3
  Inner2 w0.3: TN1.16 136.625,107.569 154.405,107.569 155.167,108.331 155.167,119.253 DRV1/RA.3
DRV1_M2: DRV1/RA.4 SWM1.3 TN1.17 | length 35.9
  Top Layer w0.3: SWM1.3 144.753,123.698 146.023,124.968 146.023,125.857 DRV1/RA.4
  Inner2 w0.3: TN1.17 133.196,106.68 133.196,118.999 136.879,122.682 141.07,122.682 DRV1/RA.4
DRV1_SR: DRV1/RA.5 DRV1/RA.6 SWPI1.1 TN1.18 | length 33.6
  Top Layer w0.3: SWPI1.1 126.965,108.72 128.37,107.315 130.529,107.315 TN1.18
  Top Layer w0.5: DRV1/RA.6 DRV1/RA.5
  Inner2 w0.3: TN1.18 132.688,108.712 132.688,119.38 DRV1/RA.6
DRV1_STP: DRV1/RA.7 SWPI1.2 TN1.20 | length 22
  Top Layer w0.3: SWPI1.2 130.148,112.776 TN1.20
  Inner2 w0.3: TN1.20 131.418,112.014 132.18,112.776 132.18,119.888 137.514,125.222 DRV1/RA.7
DRV2_1A: DRV2/DEC.12 RJ2.3 RJ2.4 | length 25.9
  Bottom Layer w0.8: DRV2/DEC.12 142.594,101.473 143.739,102.618 160.754,102.618 161.514,102.618 RJ2.3@162.534,103.638
DRV2_1B: DRV2/DEC.11 RJ2.1 RJ2.2 | length 30.5
  Bottom Layer w0.8: DRV2/DEC.11 140.054,103.505 141.207,104.658 160.754,104.658 161.514,104.658 RJ2.1@162.534,105.678
DRV2_2A: DRV2/DEC.13 RJ2.5 RJ2.6 | length 21.3
  Bottom Layer w0.8: DRV2/DEC.13 145.134,99.441 146.271,100.578 160.754,100.578 161.514,100.578 RJ2.5@162.534,101.598
DRV2_2B: DRV2/DEC.14 RJ2.7 RJ2.8 | length 17
  Bottom Layer w0.8: DRV2/DEC.14 147.674,97.79 148.422,98.538 160.754,98.538 161.514,98.538 RJ2.7@162.534,99.558
DRV2_DIR: DRV2/DEC.8 SWPI2.3 TN1.2 | length 37.1
  Top Layer w0.3: SWPI2.3 131.672,105.791 DRV2/DEC.8
  Top Layer w0.5: DRV2/DEC.8 DRV2/DEC.8@135.228,108.839
  Inner1 w0.3: TN1.2 114.4,118.364 114.4,116.332 114.908,115.824 117.067,115.824 122.147,110.744 133.323,110.744 DRV2/DEC.8
DRV2_DIR_PI: R21.2 SWPI2.4 | length 23.5
  Top Layer w0.3: SWPI2.4 120.496,105.791 122.782,108.077 122.782,125.399 R21.2
DRV2_EN: DRV2/DEC.1 TN1.9 | length 44
  Inner1 w0.3: TN1.9 119.48,98.044 142.975,98.044 152.754,107.823 DRV2/DEC.1
DRV2_M0: DRV2/DEC.2 SWM2.1 TN1.8 | length 48.8
  Top Layer w0.3: SWM2.1 144.245,103.378 149.96,109.093 DRV2/DEC.2
  Inner1 w0.3: TN1.8 119.48,100.584 141.705,100.584 DRV2/DEC.2
DRV2_M1: DRV2/DEC.3 SWM2.2 TN1.7 | length 42.8
  Top Layer w0.3: SWM2.2 144.372,104.648 147.674,107.95 DRV2/DEC.3
  Inner1 w0.3: TN1.7 119.48,103.124 141.705,103.124 DRV2/DEC.3
DRV2_M2: DRV2/DEC.4 SWM2.3 TN1.6 | length 37.6
  Top Layer w0.3: SWM2.3 144.626,105.918 145.896,107.188 145.896,108.331 DRV2/DEC.4
  Inner1 w0.3: TN1.6 116.305,109.474 120.115,105.664 141.705,105.664 DRV2/DEC.4
DRV2_SR: DRV2/DEC.5 DRV2/DEC.6 SWPI2.1 TN1.5 | length 49.6
  Top Layer w0.3: TN1.5 117.321,110.363 117.321,102.997 118.083,102.235 120.877,102.235 121.893,103.251 SWPI2.1
  Top Layer w0.5: DRV2/DEC.6 DRV2/DEC.5
  Inner1 w0.3: TN1.5 116.94,112.014 120.75,108.204 131.926,108.204 132.688,107.442 138.403,107.442 DRV2/DEC.6
DRV2_SR_PI: R23.2 SWPI2.6 | length 27.5
  Top Layer w0.3: SWPI2.6 120.496,103.251 124.306,107.061 124.306,123.519 R23.2
DRV2_STP: DRV2/DEC.7 SWPI2.2 TN1.3 | length 39.9
  Top Layer w0.3: SWPI2.2@127.481,104.521 127.989,104.521 128.497,105.029 129.132,105.029 129.642,104.519 129.642,103.884 130.402,103.124 131.545,103.124 132.18,103.759 132.18,105.283 134.466,107.569 135.99,107.569 DRV2/DEC.7
  Inner1 w0.3: TN1.3 119.099,117.094 122.909,113.284 133.323,113.284 DRV2/DEC.7
DRV2_STP_PI: R22.2 SWPI2.5 | length 25.5
  Top Layer w0.3: SWPI2.5 120.496,104.521 123.544,107.569 123.544,124.459 R22.2
DRV3_1A: DRV3/FOC.12 RJ3.3 RJ3.4 | length 32.1
  Bottom Layer w0.8: DRV3/FOC.12 102.97,104.394 107.415,99.949 107.415,92.71 109.447,90.678 113.26,90.678 RJ3.4 118.978,84.96 RJ3.3
DRV3_1B: DRV3/FOC.11 RJ3.1 RJ3.2 | length 35.7
  Bottom Layer w0.8: DRV3/FOC.11 104.24,106.934 109.955,101.219 109.955,93.091 111.098,91.948 114.03,91.948 RJ3.2 121.018,84.96 RJ3.1
DRV3_2A: DRV3/FOC.13 RJ3.5 RJ3.6 | length 28.6
  Bottom Layer w0.8: DRV3/FOC.13 101.827,101.854 104.875,98.806 104.875,92.202 107.796,89.281 112.617,89.281 RJ3.6 116.938,84.96 RJ3.5
DRV3_2B: DRV3/FOC.14 RJ3.7 RJ3.8 | length 25.4
  Bottom Layer w0.8: DRV3/FOC.14 100.938,99.314 102.589,97.663 102.589,91.313 105.891,88.011 111.847,88.011 RJ3.8 114.898,84.96 RJ3.7@114.898,84.2
DRV3_DIR: DRV3/FOC.8 U0.19 | length 19
  Bottom Layer w0.5: DRV3/FOC.8 113.511,112.903 U0.19
DRV3_M0: DRV3/FOC.2 SWM3.1 SWPI3.3 | length 44.4
  Top Layer w0.3: SWM3.1 106.907,102.87 112.622,97.155 DRV3/FOC.2
  Top Layer w0.5: v1(125.195,122.301) SWPI3.3
  Bottom Layer w0.3: DRV3/FOC.2 114.273,98.425 114.273,99.568 115.289,100.584 116.813,100.584 122.147,105.918 122.147,113.411 126.846,118.11 126.846,120.65 v1(125.195,122.301)
DRV3_M1: DRV3/FOC.3 SWM3.2 SWPI3.2 | length 37.3
  Top Layer w0.3: SWM3.2 108.177,102.743 111.479,99.441 112.502,99.441 112.622,99.322 DRV3/FOC.3
  Top Layer w0.5: v1(125.195,121.031) SWPI3.2
  Bottom Layer w0.3: DRV3/FOC.3 114.273,100.965 114.273,102.235 115.162,103.124 116.432,103.124 120.115,106.807 120.115,113.411 126.084,119.38 126.084,120.142 v1(125.195,121.031)
DRV3_M2: DRV3/FOC.4 SWM3.3 SWPI3.1 | length 31.5
  Top Layer w0.3: SWM3.3 109.447,102.616 110.844,101.219 111.987,101.219 DRV3/FOC.4
  Top Layer w0.5: v1(125.195,119.761) SWPI3.1
  Bottom Layer w0.3: DRV3/FOC.4 114.273,103.505 114.273,105.029 114.908,105.664 116.178,105.664 118.083,107.569 118.083,113.411 124.433,119.761 v1(125.195,119.761)
DRV3_SR: DRV3/FOC.5 DRV3/FOC.6 U0.16 | length 31.6
  Top Layer w0.5: DRV3/FOC.5 DRV3/FOC.6
  Bottom Layer w0.5: U0.16 109.701,131.953 109.701,129.794 108.431,128.524 108.431,111.125 DRV3/FOC.6
DRV3_STP: DRV3/FOC.7 U0.18 | length 25.5
  Bottom Layer w0.5: U0.18 112.241,131.953 112.241,129.667 110.971,128.397 110.971,111.125 DRV3/FOC.7
DRV4_1A: DRV4/ROT.12 RJ4.3 RJ4.4 | length 29
  Bottom Layer w0.8: DRV4/ROT.12 87.095,104.394 91.667,99.822 91.667,92.202 93.191,90.678 94.083,90.678 RJ4.4 99.801,84.96 RJ4.3
DRV4_1B: DRV4/ROT.11 RJ4.1 RJ4.2 | length 32.4
  Bottom Layer w0.8: DRV4/ROT.11 87.984,106.934 94.08,100.838 94.08,92.721 RJ4.2 101.841,84.96 RJ4.1
DRV4_2A: DRV4/ROT.13 RJ4.5 RJ4.6 | length 26
  Bottom Layer w0.8: DRV4/ROT.13 85.825,101.854 89.254,98.425 89.254,90.678 90.524,89.408 93.313,89.408 RJ4.6 97.761,84.96 RJ4.5
DRV4_2B: DRV4/ROT.14 RJ4.7 RJ4.8 | length 22.7
  Bottom Layer w0.8: DRV4/ROT.14 84.936,99.314 86.841,97.409 86.841,90.043 88.873,88.011 92.67,88.011 RJ4.8 95.721,84.96 RJ4.7@95.721,84.2
DRV4_DIR: DRV4/ROT.8 U0.13 | length 23.6
  Bottom Layer w0.5: DRV4/ROT.8 96.493,112.268 96.493,121.92 103.478,128.905 105.002,128.905 105.891,129.794 U0.13
DRV4_M0: DRV4/ROT.2 SWM4.1 | length 9.6
  Top Layer w0.3: SWM4.1 91.032,102.913 96.747,97.198 DRV4/ROT.2
DRV4_M1: DRV4/ROT.3 SWM4.2 | length 7.1
  Top Layer w0.3: SWM4.2 92.302,102.751 95.738,99.314 DRV4/ROT.3
DRV4_M2: DRV4/ROT.4 SWM4.3 | length 5.3
  Top Layer w0.3: SWM4.3 93.572,102.743 95.096,101.219 96.112,101.219 DRV4/ROT.4
DRV4_SR: DRV4/ROT.5 DRV4/ROT.6 U0.11 | length 31.1
  Top Layer w0.5: DRV4/ROT.5 DRV4/ROT.6
  Bottom Layer w0.5: DRV4/ROT.6 94.588,109.093 94.588,122.428 102.843,130.683 U0.11
DRV4_STP: DRV4/ROT.7 U0.15 | length 27.4
  Bottom Layer w0.5: DRV4/ROT.7 98.271,110.998 98.271,121.285 103.224,126.238 105.51,126.238 107.542,128.27 107.542,129.032 108.431,129.921 U0.15
DRV31_M0/DIR_PI: R18.2 SWPI1.4 SWPI3.4 | length 15.4
  Top Layer w0.3: R18.2 119.36,126.306 SWPI3.4 118.464,122.301 117.067,120.904 117.067,118.745 119.607,116.205 119.607,114.293 SWPI1.4
DRV31_M1/STP_PI: R19.2 SWPI1.5 SWPI3.5 | length 20.5
  Top Layer w0.3: SWPI1.5 120.838,112.776 121.004,112.942 121.004,115.57 117.575,118.999 117.575,120.65 117.956,121.031 SWPI3.5 120.838,121.031 121.385,121.578 121.385,123.952 120.623,124.714 120.623,126.643 R19.2
DRV31_M2/SR_PI: R20.2 SWPI1.6 SWPI3.6 | length 19.9
  Top Layer w0.3: SWPI1.6 120.838,111.506 122.02,112.688 122.02,118.237 121.512,118.745 121.512,119.761 ; SWPI3.6 121.512,119.761 ; R20.2 122.02,126.339 122.02,121.285 121.512,120.777 121.512,119.761
GND: C1.2 C2.2 C3.2 C4.2 C5.2 C6.2 C7.2 C8.2 C9.1 C10.2 C11.2 C12.2 C13.1 CN1.1 CN1.5 CN2.1 CN2.5 DRV1/RA.9 DRV1/RA.15 DRV2/DEC.9 DRV2/DEC.15 DRV3/FOC.1 DRV3/FOC.9 DRV3/FOC.15 DRV4/ROT.1 DRV4/ROT.9 DRV4/ROT.15 GN0.1 GPS.4 pad.15 pad.41 pad.42 pad.43 pad.44 pad.45 pad.46 RJ1.9 RJ1.10 RJ2.9 RJ2.10 RJ3.9 RJ3.10 RJ4.9 RJ4.10 TN1.G1 TN1.G2 U0.6 U0.9 U0.14 U0.20 U0.25 U0.30 U0.34 U0.39 U0.41 U0.42 U0.43 U0.44 U0.45 U0.46 U17.4 U55.1 U55.3 U55.5 U75.5 U76.3 U76.7 U76.8
  other v1: 161.67,86.709 152.246,86.741 123.671,88.392 119.48,93.091 153.897,93.218 146.785,98.679 123.163,99.187 132.815,99.314 86.333,99.692 102.208,99.695 143.991,100.711 137.26,101.346 123.163,102.003 132.815,102.235 141.324,102.485 86.333,102.87 102.208,102.997 123.576,104.521 139.038,104.529 86.333,105.664 102.208,105.664 139.546,106.68 93.572,106.807 109.447,106.807 104.728,108.395 89,108.458 119.099,108.458 121.131,110.363 104.728,110.554 89,110.617 134.212,111.125 140.943,111.506 95.604,115.824 97.382,115.824 118.337,116.078 146.785,117.237 100.43,117.475 119.861,118.364 143.991,118.364 137.006,118.999 139.038,118.999 141.451,118.999 133.143,123.277 140.054,124.333 109.701,128.016 112.241,128.016
GPIO13_PWM1: U0.33
GPIO18_PWM0: U0.12
GPIO20: U0.38
GPIO21: U0.40
GPIO26: U0.37
ID_SC: U0.28 U17.6 | length 38.2
  Top Layer w0.3: U17.6 97.232,122.832 97.763,122.301 100.303,122.301 v1(101.319,121.285)
  Inner1 w0.3: v1(101.319,121.285) 102.081,122.047 102.081,131.191 102.843,131.953 122.401,131.953 U0.28
ID_SD: U0.27 U17.5 | length 46.5
  Top Layer w0.3: U17.5 97.486,121.562 97.763,121.285 v1(100.303,121.285)
  Inner1 w0.3: v1(100.303,121.285) 99.541,122.047 99.541,133.731 100.349,134.539 124.387,134.539 124.941,133.985 124.941,131.953 U0.27
PEC: C12.1 CN1.3 CN1.7 TN1.23 | length 64.5
  Top Layer w0.3: C12.1 149.741,85.663 CN1.7
  Inner1 w0.3: TN1.23 131.672,120.396 150.849,120.396 156.564,114.681 156.564,88.265 155.772,87.473 CN1.3
  Inner1 w0.5: CN1.7 152.751,85.673 CN1.3
PPS: GPS.1 U0.22 | length 16.2
  Top Layer w0.5: GPS.1 104.621,127.635 104.621,131.445 105.121,131.945 114.9,131.945 116.051,133.096 U0.22
RA+: R27.2 TN1.13 U75.1 | length 33.5
  Top Layer w0.3: R27.2 129.005,96.139 TN1.13
  Bottom Layer w0.3: U75.1 128.323,81.581 129.386,80.518 139.165,80.518 140.308,81.661 140.308,84.836 TN1.13
RA-: R24.2 TN1.10 U75.4 | length 29.8
  Top Layer w0.3: TN1.10 117.965,99.314 R24.2
  Bottom Layer w0.3: TN1.10 117.829,99.314 122.02,95.123 122.02,92.964 130.275,84.709 132.588,84.709 134.323,82.974 U75.4
RX_ONSTEP: TN1.0 U0.24 | length 10.9
  Top Layer w0.5: TN1.0 116.686,124.714 117.702,125.73 117.702,129.286 117.321,129.667 117.321,132.461 118.083,133.223 U0.24
RXD: GPS.3 U0.10 | length 12.5
  Top Layer w0.5: U0.10 100.811,133.096 102.081,131.826 102.081,124.587 104.24,122.428 GPS.3
SCL: U0.5 U76.5 | length 74.5
  Top Layer w0.3: v1(135.355,84.709) 135.523,84.877 U76.5
  Inner2 w0.3: U0.5 95.731,123.952 107.923,111.76 107.923,93.345 111.606,89.662 124.687,89.662 128.878,85.471 134.593,85.471 v1(135.355,84.709)
SDA: U0.3 U76.6 | length 79.2
  Top Layer w0.3: U76.6 136.173,84.78 v1(136.244,84.709)
  Inner2 w0.3: U0.3 93.191,123.063 105.764,110.49 105.764,92.456 110.717,87.503 125.83,87.503 128.497,84.836 133.958,84.836 134.974,83.82 135.863,83.82 136.244,84.201 v1(136.244,84.709)
TX_ONSTEP: TN1.1 U0.21 | length 11.2
  Top Layer w0.5: TN1.1 114.908,122.174 113.511,123.571 113.511,128.651 115.543,130.683 U0.21
TXD: GPS.2 U0.8 | length 20.6
  Top Layer w0.5: U0.8 99.541,131.953 99.541,125.603 103.978,121.166 105.518,121.166 106.018,121.666 106.018,123.063 104.494,124.587 GPS.2
"": CN1.2 CN1.6 CN2.2 CN2.6 TN1.25 TN1.26 TN1.27 TN1.28 TN1.29 U0.32 U17.1 U17.2

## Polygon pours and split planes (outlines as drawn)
GND on Top Layer (solid, remove dead copper, pour order 0): 82.396,79.502 167.359,79.502 167.359,135.382 82.396,135.382
GND on Bottom Layer (solid, remove dead copper, pour order 1): 82.396,79.502 167.359,79.502 167.359,135.382 82.396,135.382
GND on Inner1 (solid, remove dead copper, pour order 2): 82.396,79.502 167.359,79.502 167.359,135.382 82.396,135.382
GND on Inner2 (solid, remove dead copper, pour order 3): 82.396,79.502 167.359,79.502 167.359,135.382 82.396,135.382

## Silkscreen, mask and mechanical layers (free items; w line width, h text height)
Top Silkscreen Layer:
  circle w0.3 net "": c85.724,121.288 r3.022
  text "PPS" at 105.974,127.349 h0.65
  text "TXD" at 105.974,124.748 h0.65
  text "EN" at 153.643,124.402 h0.65 r90
  text "M2" at 142.305,124.368 h0.84
  text "RXD" at 105.974,122.146 h0.65
  text "3.3V" at 134.292,119.607 h0.84
  text "GND" at 105.974,119.545 h0.65
  text "M0" at 142.232,118.928 h0.84
  text "DRV3[Mx] to PI" at 117.603,117.002 h0.84
  text "3.3V" at 105.946,116.943 h0.65
  text "v1.0" at 112.416,116.079 h0.97 r90
  text "3.3V" at 89.505,113.211 h0.84 r270
  text "3.3V" at 105.507,113.211 h0.84 r270
  text "DIR" at 94.307,112.371 h0.65
  text "DIR" at 110.182,112.371 h0.65
  text "GND" at 134.027,111.863 h0.65
  text "DRV1 to PI" at 118.895,108.874 h0.84
  text "EN" at 153.643,106.749 h0.65 r90
  text "M2" at 142.194,106.725 h0.84
  text "M0" at 88.937,105.315 h0.84 r270
  text "M2" at 94.379,105.302 h0.84 r270
  text "M0" at 104.812,105.315 h0.84 r270
  text "M2" at 110.254,105.302 h0.84 r270
  text "3.3V" at 134.285,101.851 h0.84
  text "M0" at 142.181,101.283 h0.84
  text "DRV2 to PI" at 118.895,100.619 h0.84
  text "GND" at 134.027,94.21 h0.65
  text "EN" at 94.154,93.403 h0.65
  text "EN" at 110.029,93.403 h0.65
  text "+12V IN" at 139.763,92.596 h0.97
  text "GND" at 139.278,85.981 h0.97
  text "ST4" at 127.144,84.407 h0.97
Bottom Silkscreen Layer:
  text "JLCJLCJLCJLC" at 160.951,133.572 h0.65
  text "A2" at 165.041,125.264 h0.65 r90
  text "DRV1" at 166.676,123.062 h0.97 r90
  text "A1" at 165.041,123.039 h0.65 r90
  text "B1" at 165.025,120.957 h0.65 r90
  text "B2" at 165.041,119.041 h0.65 r90
  text "oshwlab.com/ /  pololamag/ /  astronstep" at 100.389,115.649 h1.12
  text "A2" at 165.041,106.341 h0.65 r90
  text "A1" at 165.041,104.116 h0.65 r90
  text "DRV2" at 166.676,104.012 h0.97 r90
  text "B1" at 165.025,102.034 h0.65 r90
  text "B2" at 165.041,100.118 h0.65 r90
  text "v1.0" at 126.974,98.25 h0.97
  text "12V" at 143.883,92.203 h0.65
  text "+3.3V" at 150.955,89.003 h0.65
  text "AUX4" at 160.417,88.995 h0.65
  text "GND" at 144.001,86.507 h0.65
  text "PEC" at 150.466,83.923 h0.65
  text "AUX3" at 160.417,83.915 h0.65
  text "B2" at 96.212,82.391 h0.65
  text "B1" at 98.129,82.407 h0.65
  text "A1" at 100.211,82.391 h0.65
  text "A2" at 102.435,82.391 h0.65
  text "B2" at 115.404,82.391 h0.65
  text "B1" at 117.321,82.407 h0.65
  text "A1" at 119.403,82.391 h0.65
  text "A2" at 121.627,82.391 h0.65
  text "DRV4" at 99.923,81.105 h0.97
  text "DRV3" at 119.227,81.105 h0.97
Mech6:
  lines w0.254 net "": 81.399,113.792 106.399,113.792 106.399,130.792 81.399,130.792 81.399,113.792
